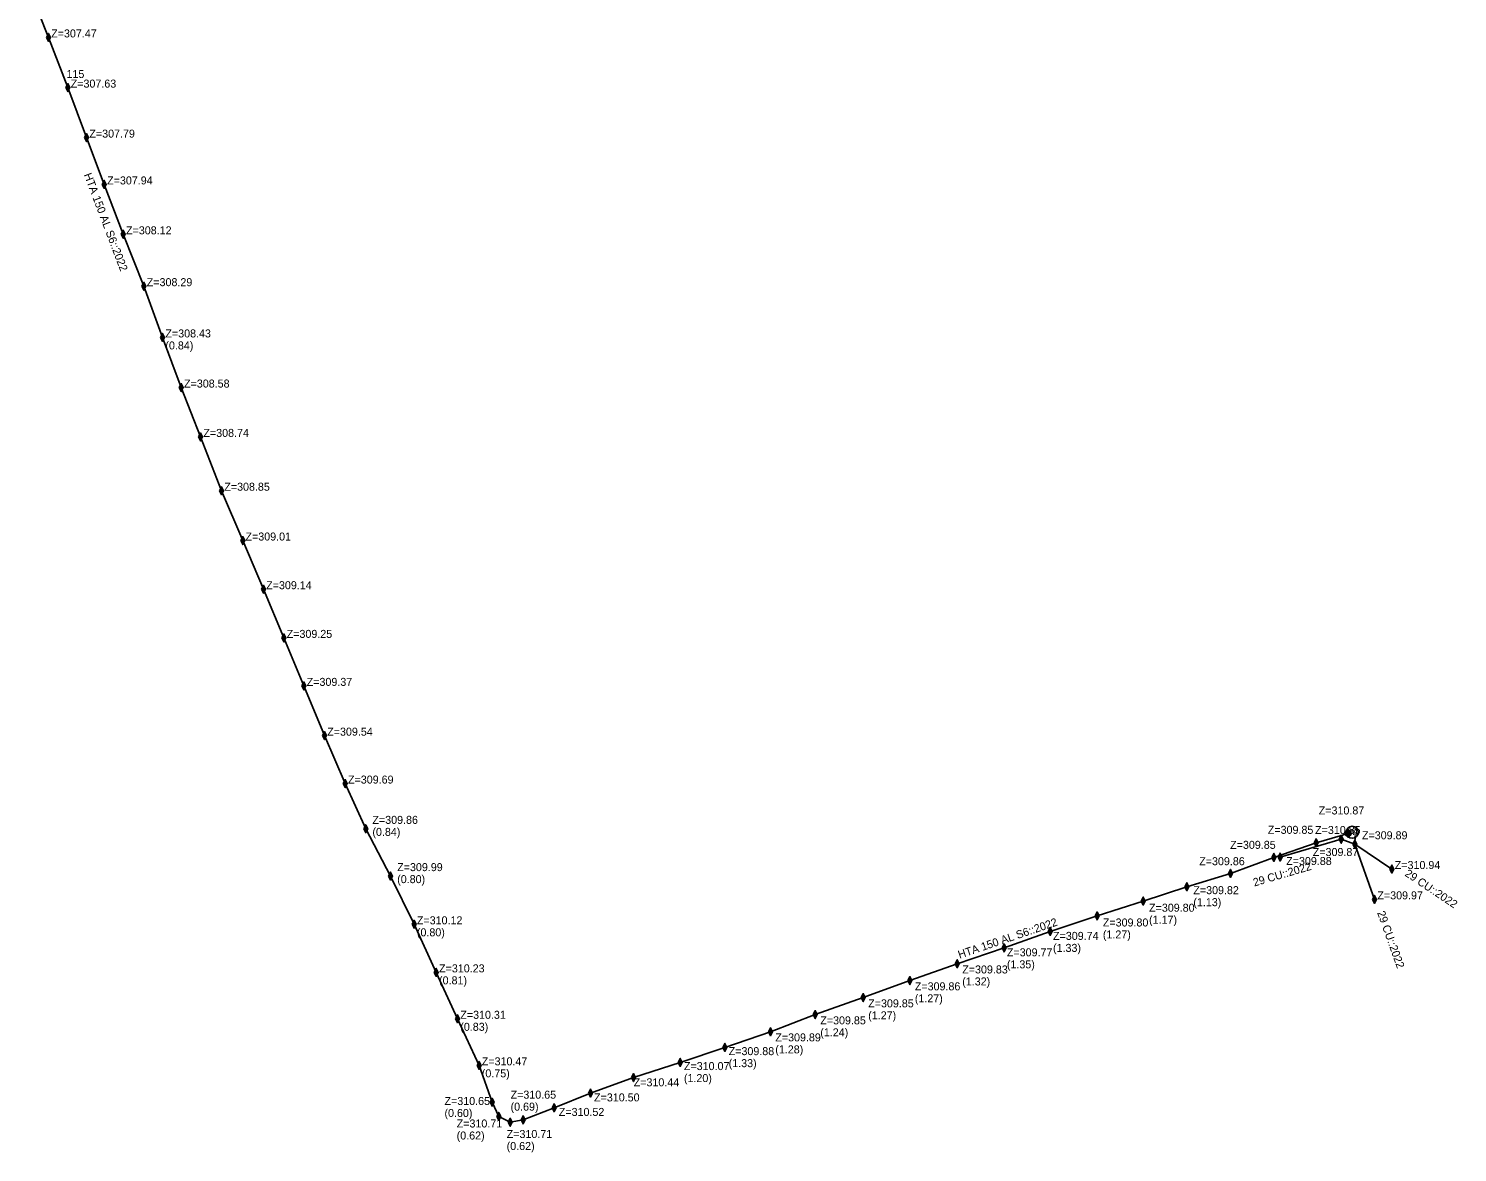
# Model space of a CAD drawing. Extents: x 799271 to 799523, y 67737 to 68184.
# Drawn here: x 799451.4 to 799522.8, y 67737.2 to 67793.3 of the extents above; entities that cross this region are included whole.
import ezdxf

# ---------------------------------------------------------------- set-up
doc = ezdxf.new("R2010")
doc.units = 0
for name, color, linetype in [('PGOC_HTA_CONSTRUIT', 7, 'Continuous'), ('PGOC_PROTECTION_MECANIQUE', 7, 'Continuous'), ('PGOC_PTRL', 7, 'Continuous'), ('PGOC_TERRE', 7, 'Continuous')]:
    doc.layers.add(name, color=color, linetype=linetype)

msp = doc.modelspace()

# ---------------------------------------------------------------- linework, layer by layer
at = {"layer": 'PGOC_HTA_CONSTRUIT'}
msp.add_lwpolyline([(799451.399, 67795.423), (799452.389, 67792.892), (799453.364, 67790.384), (799454.297, 67787.884), (799455.185, 67785.544), (799456.129, 67783.05), (799457.166, 67780.458), (799458.097, 67777.896), (799459.029, 67775.391), (799459.996, 67772.923), (799461.041, 67770.233), (799462.1, 67767.744), (799463.134, 67765.311), (799464.158, 67762.877), (799465.159, 67760.478), (799466.185, 67757.99), (799467.224, 67755.595), (799468.253, 67753.337), (799469.491, 67750.975), (799470.667, 67748.56), (799471.775, 67746.158), (799472.836, 67743.837), (799473.911, 67741.511), (799474.561, 67739.669), (799474.896, 67738.955), (799475.47, 67738.67), (799476.118, 67738.787), (799477.664, 67739.39), (799479.477, 67740.126), (799481.632, 67740.897), (799483.967, 67741.659), (799486.204, 67742.405), (799488.472, 67743.193), (799490.719, 67744.045), (799493.114, 67744.894), (799495.446, 67745.745), (799497.815, 67746.589), (799500.155, 67747.384), (799502.461, 67748.206), (799504.804, 67748.983), (799507.114, 67749.722), (799509.292, 67750.44), (799511.469, 67751.107), (799513.639, 67751.905), (799515.752, 67752.64), (799517.352, 67753.104)], dxfattribs=at)
for centre, radius in [((799517.352, 67753.104), 0.15), ((799517.559, 67753.163), 0.3)]:
    msp.add_circle(centre, radius, dxfattribs=at)
at = {"layer": 'PGOC_PTRL'}
for points in [[(799452.289, 67792.892), (799452.389, 67793.092), (799452.489, 67792.892), (799452.389, 67792.692), (799452.289, 67792.892)], [(799452.389, 67793.092), (799452.389, 67792.692)], [(799452.489, 67792.892), (799452.389, 67792.892), (799452.289, 67792.892)], [(799453.264, 67790.384), (799453.364, 67790.584), (799453.464, 67790.384), (799453.364, 67790.184), (799453.264, 67790.384)], [(799453.464, 67790.384), (799453.364, 67790.384), (799453.264, 67790.384)], [(799453.364, 67790.584), (799453.364, 67790.184)], [(799454.197, 67787.884), (799454.297, 67788.084), (799454.397, 67787.884), (799454.297, 67787.684), (799454.197, 67787.884)], [(799454.297, 67788.084), (799454.297, 67787.684)], [(799454.397, 67787.884), (799454.297, 67787.884), (799454.197, 67787.884)], [(799455.085, 67785.544), (799455.185, 67785.744), (799455.285, 67785.544), (799455.185, 67785.344), (799455.085, 67785.544)], [(799455.285, 67785.544), (799455.185, 67785.544), (799455.085, 67785.544)], [(799455.185, 67785.744), (799455.185, 67785.344)], [(799456.029, 67783.05), (799456.129, 67783.25), (799456.229, 67783.05), (799456.129, 67782.85), (799456.029, 67783.05)], [(799456.229, 67783.05), (799456.129, 67783.05), (799456.029, 67783.05)], [(799456.129, 67783.25), (799456.129, 67782.85)], [(799457.066, 67780.458), (799457.166, 67780.658), (799457.266, 67780.458), (799457.166, 67780.258), (799457.066, 67780.458)], [(799457.266, 67780.458), (799457.166, 67780.458), (799457.066, 67780.458)], [(799457.166, 67780.658), (799457.166, 67780.258)], [(799457.997, 67777.896), (799458.097, 67778.096), (799458.197, 67777.896), (799458.097, 67777.696), (799457.997, 67777.896)], [(799458.097, 67778.096), (799458.097, 67777.696)], [(799458.197, 67777.896), (799458.097, 67777.896), (799457.997, 67777.896)], [(799458.929, 67775.391), (799459.029, 67775.591), (799459.129, 67775.391), (799459.029, 67775.191), (799458.929, 67775.391)], [(799459.129, 67775.391), (799459.029, 67775.391), (799458.929, 67775.391)], [(799459.029, 67775.591), (799459.029, 67775.191)], [(799459.896, 67772.923), (799459.996, 67773.123), (799460.096, 67772.923), (799459.996, 67772.723), (799459.896, 67772.923)], [(799460.096, 67772.923), (799459.996, 67772.923), (799459.896, 67772.923)], [(799459.996, 67773.123), (799459.996, 67772.723)], [(799460.941, 67770.233), (799461.041, 67770.433), (799461.141, 67770.233), (799461.041, 67770.033), (799460.941, 67770.233)], [(799461.141, 67770.233), (799461.041, 67770.233), (799460.941, 67770.233)], [(799461.041, 67770.433), (799461.041, 67770.033)], [(799462, 67767.744), (799462.1, 67767.944), (799462.2, 67767.744), (799462.1, 67767.544), (799462, 67767.744)], [(799462.1, 67767.944), (799462.1, 67767.544)], [(799462.2, 67767.744), (799462.1, 67767.744), (799462, 67767.744)], [(799463.034, 67765.311), (799463.134, 67765.511), (799463.234, 67765.311), (799463.134, 67765.111), (799463.034, 67765.311)], [(799463.234, 67765.311), (799463.134, 67765.311), (799463.034, 67765.311)], [(799463.134, 67765.511), (799463.134, 67765.111)], [(799464.058, 67762.877), (799464.158, 67763.077), (799464.258, 67762.877), (799464.158, 67762.677), (799464.058, 67762.877)], [(799464.158, 67763.077), (799464.158, 67762.677)], [(799464.258, 67762.877), (799464.158, 67762.877), (799464.058, 67762.877)], [(799465.059, 67760.478), (799465.159, 67760.678), (799465.259, 67760.478), (799465.159, 67760.278), (799465.059, 67760.478)], [(799465.259, 67760.478), (799465.159, 67760.478), (799465.059, 67760.478)], [(799465.159, 67760.678), (799465.159, 67760.278)], [(799466.085, 67757.99), (799466.185, 67758.19), (799466.285, 67757.99), (799466.185, 67757.79), (799466.085, 67757.99)], [(799466.285, 67757.99), (799466.185, 67757.99), (799466.085, 67757.99)], [(799466.185, 67758.19), (799466.185, 67757.79)], [(799467.124, 67755.595), (799467.224, 67755.795), (799467.324, 67755.595), (799467.224, 67755.395), (799467.124, 67755.595)], [(799467.224, 67755.795), (799467.224, 67755.395)], [(799467.324, 67755.595), (799467.224, 67755.595), (799467.124, 67755.595)], [(799468.153, 67753.337), (799468.253, 67753.537), (799468.353, 67753.337), (799468.253, 67753.137), (799468.153, 67753.337)], [(799468.353, 67753.337), (799468.253, 67753.337), (799468.153, 67753.337)], [(799468.253, 67753.537), (799468.253, 67753.137)], [(799516.906, 67752.815), (799517.006, 67753.015), (799517.106, 67752.815), (799517.006, 67752.615), (799516.906, 67752.815)], [(799517.006, 67753.015), (799517.006, 67752.615)], [(799517.252, 67753.104), (799517.352, 67753.304), (799517.452, 67753.104), (799517.352, 67752.904), (799517.252, 67753.104)], [(799517.452, 67753.104), (799517.352, 67753.104), (799517.252, 67753.104)], [(799517.352, 67753.304), (799517.352, 67752.904)], [(799515.652, 67752.64), (799515.752, 67752.84), (799515.852, 67752.64), (799515.752, 67752.44), (799515.652, 67752.64)], [(799515.652, 67752.64), (799515.752, 67752.84), (799515.852, 67752.64), (799515.752, 67752.44), (799515.652, 67752.64)], [(799515.852, 67752.64), (799515.752, 67752.64), (799515.652, 67752.64)], [(799515.852, 67752.64), (799515.752, 67752.64), (799515.652, 67752.64)], [(799515.752, 67752.84), (799515.752, 67752.44)], [(799515.752, 67752.84), (799515.752, 67752.44)], [(799517.106, 67752.815), (799517.006, 67752.815), (799516.906, 67752.815)], [(799517.586, 67752.561), (799517.686, 67752.761), (799517.786, 67752.561), (799517.686, 67752.361), (799517.586, 67752.561)], [(799517.786, 67752.561), (799517.686, 67752.561), (799517.586, 67752.561)], [(799517.686, 67752.761), (799517.686, 67752.361)], [(799513.539, 67751.905), (799513.639, 67752.105), (799513.739, 67751.905), (799513.639, 67751.705), (799513.539, 67751.905)], [(799513.739, 67751.905), (799513.639, 67751.905), (799513.539, 67751.905)], [(799513.639, 67752.105), (799513.639, 67751.705)], [(799513.846, 67751.921), (799513.946, 67752.121), (799514.046, 67751.921), (799513.946, 67751.721), (799513.846, 67751.921)], [(799514.046, 67751.921), (799513.946, 67751.921), (799513.846, 67751.921)], [(799513.946, 67752.121), (799513.946, 67751.721)], [(799519.441, 67751.324), (799519.541, 67751.524), (799519.641, 67751.324), (799519.541, 67751.124), (799519.441, 67751.324)], [(799519.541, 67751.524), (799519.541, 67751.124)], [(799469.391, 67750.975), (799469.491, 67751.175), (799469.591, 67750.975), (799469.491, 67750.775), (799469.391, 67750.975)], [(799469.591, 67750.975), (799469.491, 67750.975), (799469.391, 67750.975)], [(799469.491, 67751.175), (799469.491, 67750.775)], [(799511.369, 67751.107), (799511.469, 67751.307), (799511.569, 67751.107), (799511.469, 67750.907), (799511.369, 67751.107)], [(799511.569, 67751.107), (799511.469, 67751.107), (799511.369, 67751.107)], [(799511.469, 67751.307), (799511.469, 67750.907)], [(799519.641, 67751.324), (799519.541, 67751.324), (799519.441, 67751.324)], [(799509.192, 67750.44), (799509.292, 67750.64), (799509.392, 67750.44), (799509.292, 67750.24), (799509.192, 67750.44)], [(799509.392, 67750.44), (799509.292, 67750.44), (799509.192, 67750.44)], [(799509.292, 67750.64), (799509.292, 67750.24)], [(799507.014, 67749.722), (799507.114, 67749.922), (799507.214, 67749.722), (799507.114, 67749.522), (799507.014, 67749.722)], [(799507.214, 67749.722), (799507.114, 67749.722), (799507.014, 67749.722)], [(799507.114, 67749.922), (799507.114, 67749.522)], [(799518.572, 67749.808), (799518.672, 67750.008), (799518.772, 67749.808), (799518.672, 67749.608), (799518.572, 67749.808)], [(799518.772, 67749.808), (799518.672, 67749.808), (799518.572, 67749.808)], [(799518.672, 67750.008), (799518.672, 67749.608)], [(799470.567, 67748.56), (799470.667, 67748.76), (799470.767, 67748.56), (799470.667, 67748.36), (799470.567, 67748.56)], [(799470.667, 67748.76), (799470.667, 67748.36)], [(799504.704, 67748.983), (799504.804, 67749.183), (799504.904, 67748.983), (799504.804, 67748.783), (799504.704, 67748.983)], [(799504.904, 67748.983), (799504.804, 67748.983), (799504.704, 67748.983)], [(799504.804, 67749.183), (799504.804, 67748.783)], [(799470.767, 67748.56), (799470.667, 67748.56), (799470.567, 67748.56)], [(799502.361, 67748.206), (799502.461, 67748.406), (799502.561, 67748.206), (799502.461, 67748.006), (799502.361, 67748.206)], [(799502.561, 67748.206), (799502.461, 67748.206), (799502.361, 67748.206)], [(799502.461, 67748.406), (799502.461, 67748.006)], [(799500.055, 67747.384), (799500.155, 67747.584), (799500.255, 67747.384), (799500.155, 67747.184), (799500.055, 67747.384)], [(799500.255, 67747.384), (799500.155, 67747.384), (799500.055, 67747.384)], [(799500.155, 67747.584), (799500.155, 67747.184)], [(799497.715, 67746.589), (799497.815, 67746.789), (799497.915, 67746.589), (799497.815, 67746.389), (799497.715, 67746.589)], [(799497.915, 67746.589), (799497.815, 67746.589), (799497.715, 67746.589)], [(799497.815, 67746.789), (799497.815, 67746.389)], [(799471.675, 67746.158), (799471.775, 67746.358), (799471.875, 67746.158), (799471.775, 67745.958), (799471.675, 67746.158)], [(799471.875, 67746.158), (799471.775, 67746.158), (799471.675, 67746.158)], [(799471.775, 67746.358), (799471.775, 67745.958)], [(799495.346, 67745.745), (799495.446, 67745.945), (799495.546, 67745.745), (799495.446, 67745.545), (799495.346, 67745.745)], [(799495.446, 67745.945), (799495.446, 67745.545)], [(799493.014, 67744.894), (799493.114, 67745.094), (799493.214, 67744.894), (799493.114, 67744.694), (799493.014, 67744.894)], [(799493.114, 67745.094), (799493.114, 67744.694)], [(799495.546, 67745.745), (799495.446, 67745.745), (799495.346, 67745.745)], [(799493.214, 67744.894), (799493.114, 67744.894), (799493.014, 67744.894)], [(799472.736, 67743.837), (799472.836, 67744.037), (799472.936, 67743.837), (799472.836, 67743.637), (799472.736, 67743.837)], [(799472.936, 67743.837), (799472.836, 67743.837), (799472.736, 67743.837)], [(799472.836, 67744.037), (799472.836, 67743.637)], [(799490.619, 67744.045), (799490.719, 67744.245), (799490.819, 67744.045), (799490.719, 67743.845), (799490.619, 67744.045)], [(799490.819, 67744.045), (799490.719, 67744.045), (799490.619, 67744.045)], [(799490.719, 67744.245), (799490.719, 67743.845)], [(799488.372, 67743.193), (799488.472, 67743.393), (799488.572, 67743.193), (799488.472, 67742.993), (799488.372, 67743.193)], [(799488.572, 67743.193), (799488.472, 67743.193), (799488.372, 67743.193)], [(799488.472, 67743.393), (799488.472, 67742.993)], [(799486.104, 67742.405), (799486.204, 67742.605), (799486.304, 67742.405), (799486.204, 67742.205), (799486.104, 67742.405)], [(799486.304, 67742.405), (799486.204, 67742.405), (799486.104, 67742.405)], [(799486.204, 67742.605), (799486.204, 67742.205)], [(799473.811, 67741.511), (799473.911, 67741.711), (799474.011, 67741.511), (799473.911, 67741.311), (799473.811, 67741.511)], [(799474.011, 67741.511), (799473.911, 67741.511), (799473.811, 67741.511)], [(799473.911, 67741.711), (799473.911, 67741.311)], [(799483.867, 67741.659), (799483.967, 67741.859), (799484.067, 67741.659), (799483.967, 67741.459), (799483.867, 67741.659)], [(799484.067, 67741.659), (799483.967, 67741.659), (799483.867, 67741.659)], [(799483.967, 67741.859), (799483.967, 67741.459)], [(799481.532, 67740.897), (799481.632, 67741.097), (799481.732, 67740.897), (799481.632, 67740.697), (799481.532, 67740.897)], [(799481.732, 67740.897), (799481.632, 67740.897), (799481.532, 67740.897)], [(799481.632, 67741.097), (799481.632, 67740.697)], [(799479.377, 67740.126), (799479.477, 67740.326), (799479.577, 67740.126), (799479.477, 67739.926), (799479.377, 67740.126)], [(799479.577, 67740.126), (799479.477, 67740.126), (799479.377, 67740.126)], [(799479.477, 67740.326), (799479.477, 67739.926)], [(799474.461, 67739.669), (799474.561, 67739.869), (799474.661, 67739.669), (799474.561, 67739.469), (799474.461, 67739.669)], [(799474.661, 67739.669), (799474.561, 67739.669), (799474.461, 67739.669)], [(799474.561, 67739.869), (799474.561, 67739.469)], [(799477.564, 67739.39), (799477.664, 67739.59), (799477.764, 67739.39), (799477.664, 67739.19), (799477.564, 67739.39)], [(799477.764, 67739.39), (799477.664, 67739.39), (799477.564, 67739.39)], [(799477.664, 67739.59), (799477.664, 67739.19)], [(799474.796, 67738.955), (799474.896, 67739.155), (799474.996, 67738.955), (799474.896, 67738.755), (799474.796, 67738.955)], [(799474.996, 67738.955), (799474.896, 67738.955), (799474.796, 67738.955)], [(799474.896, 67739.155), (799474.896, 67738.755)], [(799475.37, 67738.67), (799475.47, 67738.87), (799475.57, 67738.67), (799475.47, 67738.47), (799475.37, 67738.67)], [(799475.57, 67738.67), (799475.47, 67738.67), (799475.37, 67738.67)], [(799475.47, 67738.87), (799475.47, 67738.47)], [(799476.018, 67738.787), (799476.118, 67738.987), (799476.218, 67738.787), (799476.118, 67738.587), (799476.018, 67738.787)], [(799476.218, 67738.787), (799476.118, 67738.787), (799476.018, 67738.787)], [(799476.118, 67738.987), (799476.118, 67738.587)]]:
    msp.add_lwpolyline(points, dxfattribs=at)
at = {"layer": 'PGOC_TERRE'}
for points in [[(799517.698, 67752.997), (799517.686, 67752.561), (799519.541, 67751.324)], [(799517.686, 67752.561), (799517.006, 67752.815), (799513.946, 67751.921)], [(799517.686, 67752.561), (799518.672, 67749.808)]]:
    msp.add_lwpolyline(points, dxfattribs=at)

# ---------------------------------------------------------------- texts
at = {"layer": 'PGOC_HTA_CONSTRUIT'}
for rotation, p in [(290.72985, (799454.155, 67786.029)), (18.76234, (799497.93, 67746.839))]:
    msp.add_text('HTA 150 AL S6::2022', height=0.4, rotation=rotation, dxfattribs=at).set_placement(p)
msp.add_text('W', height=0.3, dxfattribs=at).set_placement((799517.347, 67753.025))
at = {"layer": 'PGOC_PROTECTION_MECANIQUE'}
for rotation, p in [(16.28123, (799512.664, 67750.449)), (326.28079, (799520.148, 67751.01)), (289.69638, (799518.794, 67749.147))]:
    msp.add_text('29 CU::2022', height=0.4, rotation=rotation, dxfattribs=at).set_placement(p)
at = {"layer": 'PGOC_PTRL'}
for s, p in [('Z=307.47', (799452.529, 67792.892)), ('115', (799453.294, 67790.864)), ('Z=307.63', (799453.504, 67790.384)), ('Z=307.79', (799454.437, 67787.884)), ('Z=307.94', (799455.325, 67785.544)), ('Z=308.12', (799456.269, 67783.05)), ('Z=308.29', (799457.306, 67780.458)), ('Z=308.43', (799458.237, 67777.896)), ('(0.84)', (799458.237, 67777.296)), ('Z=308.58', (799459.169, 67775.391)), ('Z=308.74', (799460.136, 67772.923)), ('Z=308.85', (799461.181, 67770.233)), ('Z=309.01', (799462.24, 67767.744)), ('Z=309.14', (799463.274, 67765.311)), ('Z=309.25', (799464.298, 67762.877)), ('Z=309.37', (799465.299, 67760.478)), ('Z=309.54', (799466.325, 67757.99)), ('Z=309.69', (799467.364, 67755.595)), ('Z=310.87', (799515.881, 67754.052)), ('Z=309.86', (799468.584, 67753.581)), ('(0.84)', (799468.584, 67752.981)), ('Z=309.85', (799513.336, 67753.083)), ('Z=310.85', (799515.699, 67753.076)), ('1', (799517.616, 67753.041)), ('Z=309.89', (799518.041, 67752.811)), ('Z=309.85', (799511.453, 67752.333)), ('Z=309.87', (799515.583, 67751.973)), ('Z=309.99', (799469.822, 67751.219)), ('Z=309.86', (799509.907, 67751.514)), ('Z=309.88', (799514.254, 67751.524)), ('Z=310.94', (799519.681, 67751.324)), ('(0.80)', (799469.822, 67750.619)), ('Z=309.82', (799509.613, 67750.067)), ('Z=309.97', (799518.812, 67749.808)), ('Z=309.80', (799507.401, 67749.19)), ('(1.13)', (799509.613, 67749.467)), ('Z=310.12', (799470.807, 67748.56)), ('Z=309.80', (799505.091, 67748.452)), ('(1.17)', (799507.401, 67748.59)), ('(0.80)', (799470.807, 67747.96)), ('Z=309.74', (799502.601, 67747.782)), ('(1.27)', (799505.091, 67747.852)), ('Z=309.77', (799500.295, 67746.96)), ('(1.33)', (799502.601, 67747.182)), ('Z=310.23', (799471.915, 67746.158)), ('Z=309.83', (799498.063, 67746.104)), ('(1.35)', (799500.295, 67746.36)), ('(0.81)', (799471.915, 67745.558)), ('(1.32)', (799498.063, 67745.504)), ('Z=309.86', (799495.694, 67745.26)), ('(1.27)', (799495.694, 67744.66)), ('Z=309.85', (799493.363, 67744.409)), ('Z=310.31', (799472.976, 67743.837)), ('(0.83)', (799472.976, 67743.237)), ('Z=309.85', (799490.968, 67743.56)), ('(1.27)', (799493.363, 67743.809)), ('Z=309.89', (799488.72, 67742.708)), ('(1.24)', (799490.968, 67742.96)), ('Z=309.88', (799486.389, 67742.02)), ('(1.28)', (799488.72, 67742.108)), ('Z=310.47', (799474.051, 67741.511)), ('Z=310.07', (799484.153, 67741.274)), ('(1.33)', (799486.389, 67741.42)), ('(0.75)', (799474.051, 67740.911)), ('Z=310.44', (799481.642, 67740.462)), ('(1.20)', (799484.153, 67740.674)), ('Z=310.65', (799475.489, 67739.845)), ('Z=310.50', (799479.662, 67739.708)), ('Z=310.65', (799472.186, 67739.529)), ('(0.69)', (799475.489, 67739.245)), ('Z=310.52', (799477.9, 67738.982)), ('(0.60)', (799472.186, 67738.929)), ('Z=310.71', (799472.795, 67738.404)), ('(0.62)', (799472.795, 67737.804)), ('Z=310.71', (799475.294, 67737.878)), ('(0.62)', (799475.294, 67737.278))]:
    msp.add_text(s, height=0.4, dxfattribs=at).set_placement(p)

doc.saveas('drawing.dxf')
